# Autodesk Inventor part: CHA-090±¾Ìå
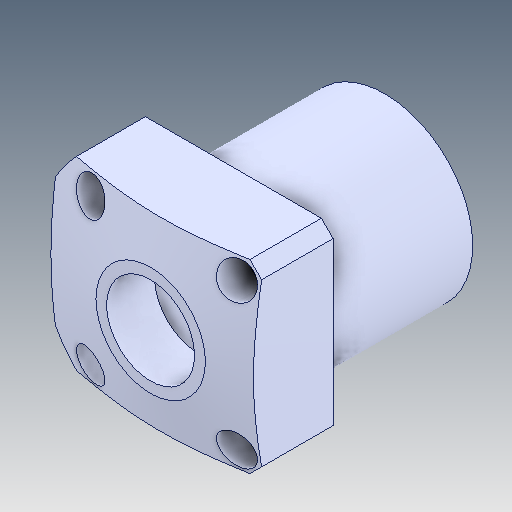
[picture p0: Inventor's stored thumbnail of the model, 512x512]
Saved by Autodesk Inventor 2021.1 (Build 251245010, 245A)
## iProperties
Created: 2021-05
Part Number: CHA-090±¾Ìå
Material: Ogólny
Document SubType Name: Modeling
Designer: user
Density: 1 g/cm^3
Appearance: Domyślna
Author: user
Revision Number: ÈÎºÎ
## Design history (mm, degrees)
feature "µ¹½Ç1"
node "Bryła1"
